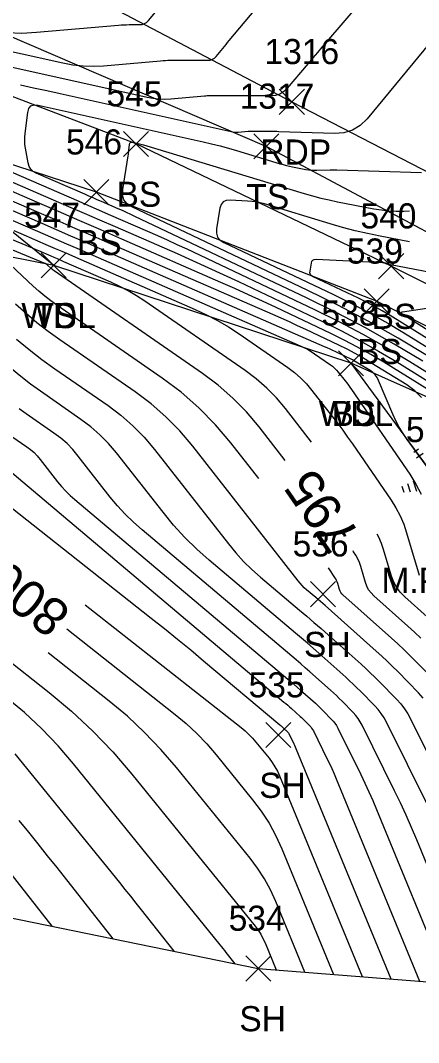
# Model space of a CAD drawing. Extents: x 1650836 to 1652450, y 332578 to 333908.
# Drawn here: x 1652260.8 to 1652292.5, y 332609.5 to 332690.8 of the extents above; entities that cross this region are included whole.
import ezdxf

# ---------------------------------------------------------------- set-up
doc = ezdxf.new("R2010")
doc.units = 0
for name, color, linetype in [('L_A', 7, 'Continuous'), ('L_C', 7, 'Continuous'), ('L_I', 7, 'Continuous'), ('L_TIC', 7, 'Continuous'), ('LAWA', 7, 'Continuous'), ('LELB', 7, 'Continuous'), ('LSOGCMA', 7, 'Continuous'), ('LSOGCMA_T', 7, 'Continuous'), ('LSOGCMI', 7, 'Continuous'), ('LSOGP', 7, 'Continuous'), ('LTC', 7, 'Continuous'), ('P_A', 7, 'Continuous'), ('P_I', 7, 'Continuous'), ('P_TIC', 7, 'Continuous'), ('PET', 7, 'Continuous')]:
    doc.layers.add(name, color=color, linetype=linetype)

msp = doc.modelspace()

# ---------------------------------------------------------------- linework, layer by layer
at = {"layer": 'L_TIC'}
for points in [[(1652268.989, 332680.007), (1652270.989, 332682.007)], [(1652270.989, 332680.007), (1652268.989, 332682.007)], [(1652279.373, 332679.816), (1652281.373, 332681.816)], [(1652281.373, 332679.816), (1652279.373, 332681.816)], [(1652265.826, 332676.17), (1652267.826, 332678.17)], [(1652267.826, 332676.17), (1652265.826, 332678.17)], [(1652262.425, 332670.343), (1652264.425, 332672.343)], [(1652264.425, 332670.343), (1652262.425, 332672.343)], [(1652262.425, 332670.343), (1652264.425, 332672.343)], [(1652264.425, 332670.343), (1652262.425, 332672.343)], [(1652289.321, 332670.283), (1652291.321, 332672.283)], [(1652291.321, 332670.283), (1652289.321, 332672.283)], [(1652288.164, 332667.483), (1652290.164, 332669.483)], [(1652290.164, 332667.483), (1652288.164, 332669.483)], [(1652286.129, 332662.549), (1652288.129, 332664.549)], [(1652288.129, 332662.549), (1652286.129, 332664.549)], [(1652286.129, 332662.549), (1652288.129, 332664.549)], [(1652288.129, 332662.549), (1652286.129, 332664.549)], [(1652283.883, 332644.163), (1652285.883, 332646.163)], [(1652285.883, 332644.163), (1652283.883, 332646.163)], [(1652280.322, 332632.943), (1652282.322, 332634.943)], [(1652282.322, 332632.943), (1652280.322, 332634.943)], [(1652278.734, 332614.362), (1652280.734, 332616.362)], [(1652280.734, 332614.362), (1652278.734, 332616.362)]]:
    msp.add_lwpolyline(points, dxfattribs=at)
at = {"layer": 'LAWA'}
msp.add_lwpolyline([(1652377.083, 332609.462), (1652362.423, 332618.359), (1652352.896, 332629.018), (1652326.723, 332645.943), (1652287.129, 332663.549), (1652263.425, 332671.343), (1652249.055, 332682.968), (1652227.219, 332684.809), (1652198.28, 332683.973), (1652188.25, 332681.448)], dxfattribs=at)
at = {"layer": 'LELB'}
for points in [[(1652226.417, 332702.923), (1652236.723, 332699.587), (1652280.373, 332680.816), (1652330.286, 332654.264), (1652363.786, 332637.255), (1652386.916, 332625.064)], [(1652382.141, 332616.979), (1652358.657, 332634.506), (1652330.255, 332651.361), (1652290.321, 332671.283), (1652269.989, 332681.007), (1652251.521, 332688.043), (1652226.806, 332692.532), (1652196.733, 332693.642), (1652183.53, 332688.882)], [(1652365.04, 332620.431), (1652356.315, 332631.256), (1652328.76, 332648.708), (1652289.164, 332668.483), (1652266.826, 332677.17), (1652249.055, 332682.968)], [(1652263.425, 332671.343), (1652250.6, 332673.853), (1652230.367, 332676.723), (1652213.745, 332678.986)], [(1652357.687, 332613.243), (1652345.655, 332623.271), (1652322.133, 332635.513), (1652299.743, 332646.435), (1652287.129, 332663.549)]]:
    msp.add_lwpolyline(points, dxfattribs=at)
at = {"layer": 'LSOGCMA'}
for points in [[(1652293.221, 332664.146), (1652290.875, 332665.556), (1652288.492, 332666.898), (1652286.072, 332668.172), (1652283.616, 332669.379), (1652269.65, 332675.996), (1652269.273, 332676.24), (1652269.026, 332676.553), (1652268.909, 332676.933), (1652268.922, 332677.383), (1652269.356, 332680.058), (1652269.374, 332680.171), (1652269.39, 332680.284), (1652269.406, 332680.397), (1652269.421, 332680.511), (1652269.479, 332680.972), (1652269.504, 332681.065), (1652269.553, 332681.124), (1652269.625, 332681.151), (1652269.721, 332681.143), (1652270.152, 332681.048), (1652270.259, 332681.023), (1652270.366, 332680.996), (1652270.473, 332680.967), (1652270.579, 332680.936), (1652283.376, 332677.07), (1652284.04, 332676.879), (1652284.707, 332676.705), (1652285.379, 332676.549), (1652286.056, 332676.41), (1652288.947, 332675.854), (1652289.538, 332675.757), (1652290.131, 332675.694), (1652290.727, 332675.663), (1652291.325, 332675.666), (1652291.78, 332675.68)], [(1652281.875, 332655.819), (1652279.794, 332658.477), (1652278.786, 332659.671), (1652277.696, 332660.779), (1652276.525, 332661.8), (1652275.274, 332662.736), (1652263.461, 332670.9), (1652263.392, 332670.95), (1652263.325, 332671.002), (1652263.26, 332671.056), (1652263.197, 332671.113), (1652262.949, 332671.344), (1652262.885, 332671.399), (1652262.817, 332671.448), (1652262.744, 332671.489), (1652262.668, 332671.525), (1652252.714, 332675.625)], [(1652292.699, 332641.652), (1652292.178, 332642.14), (1652291.649, 332642.619), (1652288.942, 332645.029), (1652288.715, 332645.261), (1652288.526, 332645.516), (1652288.375, 332645.796), (1652288.263, 332646.101), (1652287.891, 332647.366), (1652287.786, 332647.677), (1652287.657, 332647.977), (1652287.506, 332648.265), (1652287.331, 332648.543), (1652287.281, 332648.615)], [(1652264.46, 332642.402), (1652273.11, 332635.592), (1652273.992, 332634.856), (1652274.831, 332634.075), (1652275.624, 332633.249), (1652276.373, 332632.377), (1652279.277, 332628.798), (1652279.967, 332627.882), (1652280.586, 332626.923), (1652281.133, 332625.922), (1652281.608, 332624.878), (1652285.728, 332614.89)]]:
    msp.add_lwpolyline(points, dxfattribs=at)
at = {"layer": 'LSOGCMI'}
for points in [[(1652247.518, 332690.967), (1652249.349, 332690.7), (1652251.169, 332690.342), (1652264.157, 332687.455), (1652264.963, 332687.307), (1652265.774, 332687.223), (1652266.588, 332687.2), (1652267.407, 332687.241), (1652271.947, 332687.637), (1652272.139, 332687.652), (1652272.331, 332687.662), (1652272.524, 332687.669), (1652272.716, 332687.671), (1652275.7, 332687.669), (1652275.896, 332687.689), (1652276.073, 332687.748), (1652276.232, 332687.846), (1652276.372, 332687.985), (1652276.895, 332688.617), (1652277.026, 332688.775), (1652277.158, 332688.933), (1652277.289, 332689.09), (1652277.421, 332689.248), (1652283.655, 332696.668)], [(1652289.075, 332693.707), (1652285.172, 332689.147), (1652284.804, 332688.717), (1652284.438, 332688.286), (1652284.072, 332687.855), (1652283.707, 332687.423), (1652282.042, 332685.452), (1652281.762, 332685.18), (1652281.446, 332684.986), (1652281.093, 332684.87), (1652280.705, 332684.831), (1652275.884, 332684.834), (1652275.771, 332684.833), (1652275.659, 332684.829), (1652275.546, 332684.823), (1652275.433, 332684.815), (1652272.772, 332684.582), (1652272.292, 332684.559), (1652271.814, 332684.572), (1652271.339, 332684.621), (1652270.867, 332684.708), (1652251.368, 332689.042)], [(1652248.897, 332692.103), (1652257.448, 332690.202), (1652258.588, 332689.994), (1652259.733, 332689.874), (1652260.885, 332689.842), (1652262.042, 332689.899), (1652268.58, 332690.47), (1652268.792, 332690.486), (1652269.004, 332690.498), (1652269.216, 332690.505), (1652269.428, 332690.507), (1652270.278, 332690.507), (1652270.48, 332690.527), (1652270.664, 332690.588), (1652270.827, 332690.691), (1652270.972, 332690.835), (1652271.526, 332691.511)], [(1652294.668, 332690.604), (1652288.401, 332683.016), (1652287.86, 332682.484), (1652287.247, 332682.112), (1652286.562, 332681.898), (1652285.805, 332681.844), (1652281.372, 332681.986), (1652281.21, 332681.991), (1652281.048, 332681.994), (1652280.886, 332681.996), (1652280.724, 332681.997), (1652279.052, 332681.998), (1652279.019, 332681.998), (1652278.986, 332681.997), (1652278.953, 332681.995), (1652278.92, 332681.992), (1652278.137, 332681.924), (1652277.995, 332681.917), (1652277.855, 332681.921), (1652277.715, 332681.935), (1652277.576, 332681.961), (1652263.937, 332684.993), (1652262.882, 332685.227), (1652261.827, 332685.461), (1652260.772, 332685.695)], [(1652292.838, 332663.712), (1652290.574, 332665.072), (1652288.274, 332666.368), (1652285.938, 332667.598), (1652283.567, 332668.762), (1652269.892, 332675.243), (1652269.562, 332675.397), (1652269.231, 332675.549), (1652268.899, 332675.699), (1652268.566, 332675.846), (1652267.23, 332676.428), (1652266.896, 332676.573), (1652266.562, 332676.718), (1652266.228, 332676.863), (1652265.894, 332677.007), (1652262.038, 332678.674), (1652261.792, 332678.814), (1652261.601, 332678.998), (1652261.466, 332679.226), (1652261.386, 332679.498), (1652261.176, 332680.671), (1652261.135, 332680.965), (1652261.116, 332681.259), (1652261.119, 332681.554), (1652261.145, 332681.85), (1652261.353, 332683.511), (1652261.44, 332683.829), (1652261.608, 332684.033), (1652261.856, 332684.123), (1652262.185, 332684.098), (1652275.341, 332681.182), (1652276.012, 332681.027), (1652276.68, 332680.859), (1652277.345, 332680.678), (1652278.007, 332680.485), (1652281.479, 332679.436), (1652281.723, 332679.366), (1652281.969, 332679.302), (1652282.217, 332679.244), (1652282.466, 332679.193), (1652283.531, 332678.988), (1652283.749, 332678.952), (1652283.967, 332678.929), (1652284.187, 332678.918), (1652284.407, 332678.919), (1652285.472, 332678.953), (1652285.602, 332678.956), (1652285.733, 332678.957), (1652285.863, 332678.956), (1652285.993, 332678.953), (1652292.734, 332678.736)], [(1652249.728, 332682.471), (1652263.382, 332676.57), (1652264.617, 332676.036), (1652265.852, 332675.5), (1652267.086, 332674.964), (1652268.32, 332674.427), (1652273.255, 332672.277), (1652274.486, 332671.734), (1652275.714, 332671.182), (1652276.936, 332670.62), (1652278.155, 332670.049), (1652284.859, 332666.872), (1652286.37, 332666.13), (1652287.859, 332665.346), (1652289.325, 332664.52), (1652290.768, 332663.653), (1652297.985, 332659.178)], [(1652255.585, 332680.701), (1652264.638, 332676.789), (1652265.423, 332676.449), (1652266.207, 332676.109), (1652266.991, 332675.768), (1652267.775, 332675.427), (1652270.91, 332674.061), (1652271.693, 332673.717), (1652272.472, 332673.366), (1652273.249, 332673.009), (1652274.023, 332672.646), (1652284.213, 332667.817), (1652286.154, 332666.864), (1652288.066, 332665.857), (1652289.949, 332664.796), (1652291.803, 332663.682), (1652302.19, 332657.241)], [(1652294.486, 332660.676), (1652289.733, 332663.624), (1652288.7, 332664.244), (1652287.651, 332664.835), (1652286.586, 332665.396), (1652285.504, 332665.927), (1652281.146, 332667.992), (1652280.054, 332668.504), (1652278.959, 332669.008), (1652277.859, 332669.502), (1652276.756, 332669.988), (1652268.865, 332673.427), (1652267.181, 332674.16), (1652265.496, 332674.891), (1652263.811, 332675.622), (1652262.126, 332676.351), (1652252.215, 332680.635)], [(1652292.743, 332660.813), (1652292.198, 332661.355), (1652291.561, 332661.818), (1652288.698, 332663.594), (1652288.076, 332663.968), (1652287.444, 332664.324), (1652286.802, 332664.662), (1652286.15, 332664.982), (1652283.524, 332666.226), (1652282.867, 332666.535), (1652282.206, 332666.838), (1652281.544, 332667.136), (1652280.879, 332667.429), (1652268.013, 332673.035), (1652266.578, 332673.66), (1652265.142, 332674.284), (1652263.705, 332674.906), (1652262.268, 332675.528), (1652254.701, 332678.798)], [(1652283.978, 332657.277), (1652281.899, 332659.933), (1652281.18, 332660.784), (1652280.403, 332661.574), (1652279.569, 332662.302), (1652278.676, 332662.97), (1652270.681, 332668.495), (1652270.034, 332668.92), (1652269.369, 332669.311), (1652268.686, 332669.67), (1652267.985, 332669.996), (1652264.22, 332671.636), (1652263.971, 332671.744), (1652263.722, 332671.852), (1652263.474, 332671.96), (1652263.225, 332672.068), (1652262.228, 332672.499), (1652261.979, 332672.606), (1652261.73, 332672.712), (1652261.479, 332672.817), (1652261.229, 332672.92), (1652252.211, 332676.635)], [(1652294.336, 332653.747), (1652291.594, 332657.487), (1652291.266, 332657.961), (1652290.968, 332658.452), (1652290.699, 332658.959), (1652290.458, 332659.482), (1652289.316, 332662.169), (1652289.193, 332662.407), (1652289.039, 332662.618), (1652288.854, 332662.803), (1652288.637, 332662.96), (1652287.663, 332663.565), (1652287.451, 332663.692), (1652287.236, 332663.813), (1652287.018, 332663.928), (1652286.796, 332664.037), (1652285.902, 332664.46), (1652285.679, 332664.565), (1652285.454, 332664.668), (1652285.229, 332664.77), (1652285.002, 332664.869), (1652267.065, 332672.685), (1652265.926, 332673.181), (1652264.787, 332673.676), (1652263.647, 332674.17), (1652262.507, 332674.663), (1652257.188, 332676.962)], [(1652291.789, 332673.214), (1652289.451, 332673.664), (1652288.444, 332673.871), (1652287.444, 332674.104), (1652286.45, 332674.362), (1652285.463, 332674.647), (1652280.222, 332676.23), (1652279.888, 332676.32), (1652279.55, 332676.389), (1652279.209, 332676.438), (1652278.864, 332676.465), (1652277.477, 332676.534), (1652277.167, 332676.507), (1652276.93, 332676.389), (1652276.765, 332676.181), (1652276.673, 332675.884), (1652276.41, 332674.261), (1652276.399, 332673.903), (1652276.492, 332673.6), (1652276.689, 332673.352), (1652276.989, 332673.158), (1652285.661, 332669.049), (1652287.212, 332668.287), (1652288.74, 332667.482), (1652290.244, 332666.635), (1652291.725, 332665.745), (1652314.805, 332651.431)], [(1652259.374, 332675.256), (1652262.746, 332673.798), (1652263.589, 332673.433), (1652264.432, 332673.068), (1652265.275, 332672.702), (1652266.117, 332672.335), (1652283.071, 332664.948), (1652283.369, 332664.81), (1652283.659, 332664.657), (1652283.941, 332664.491), (1652284.216, 332664.311), (1652285.481, 332663.436), (1652285.655, 332663.306), (1652285.818, 332663.164), (1652285.969, 332663.01), (1652286.11, 332662.844), (1652286.648, 332662.157), (1652286.781, 332661.984), (1652286.911, 332661.809), (1652287.039, 332661.632), (1652287.164, 332661.453), (1652291.798, 332654.713), (1652292.293, 332653.93), (1652292.721, 332653.114)], [(1652260.255, 332674.112), (1652260.801, 332673.877), (1652262.985, 332672.933), (1652263.531, 332672.697), (1652264.077, 332672.46), (1652264.623, 332672.223), (1652265.168, 332671.986), (1652274.69, 332667.837), (1652275.603, 332667.413), (1652276.493, 332666.946), (1652277.358, 332666.436), (1652278.2, 332665.884), (1652282.079, 332663.203), (1652282.612, 332662.804), (1652283.111, 332662.369), (1652283.575, 332661.897), (1652284.004, 332661.389), (1652285.654, 332659.281), (1652286.062, 332658.751), (1652286.462, 332658.215), (1652286.854, 332657.673), (1652287.237, 332657.124), (1652290.309, 332652.657), (1652290.697, 332652.042), (1652291.033, 332651.402), (1652291.318, 332650.738), (1652291.55, 332650.048), (1652292.541, 332646.683)], [(1652319.01, 332649.495), (1652290.23, 332667.344), (1652289.613, 332667.714), (1652288.987, 332668.067), (1652288.352, 332668.402), (1652287.706, 332668.719), (1652284.098, 332670.428), (1652283.973, 332670.509), (1652283.891, 332670.613), (1652283.852, 332670.739), (1652283.857, 332670.888), (1652283.961, 332671.528), (1652284.004, 332671.667), (1652284.081, 332671.764), (1652284.191, 332671.819), (1652284.336, 332671.832), (1652289.624, 332671.568), (1652289.68, 332671.564), (1652289.735, 332671.556), (1652289.789, 332671.545), (1652289.843, 332671.531), (1652290.057, 332671.466), (1652290.111, 332671.45), (1652290.165, 332671.436), (1652290.219, 332671.424), (1652290.274, 332671.412), (1652300.525, 332669.443)], [(1652279.772, 332654.36), (1652277.542, 332657.209), (1652276.321, 332658.655), (1652275.001, 332659.996), (1652273.584, 332661.234), (1652272.068, 332662.367), (1652263.684, 332668.161), (1652263.189, 332668.517), (1652262.708, 332668.89), (1652262.241, 332669.28), (1652261.788, 332669.688), (1652260.005, 332671.354)], [(1652292.882, 332636.884), (1652292.488, 332637.318), (1652290.84, 332638.999), (1652290.424, 332639.415), (1652290.002, 332639.824), (1652289.573, 332640.227), (1652289.137, 332640.621), (1652285.061, 332644.249), (1652284.878, 332644.411), (1652284.694, 332644.571), (1652284.509, 332644.73), (1652284.323, 332644.888), (1652283.576, 332645.517), (1652283.394, 332645.679), (1652283.221, 332645.849), (1652283.057, 332646.028), (1652282.902, 332646.216), (1652274.503, 332656.946), (1652273.478, 332658.159), (1652272.372, 332659.284), (1652271.183, 332660.322), (1652269.912, 332661.272), (1652263.907, 332665.423), (1652262.986, 332666.084), (1652262.091, 332666.778), (1652261.222, 332667.505), (1652260.38, 332668.263)], [(1652296.859, 332663.913), (1652291.109, 332667.508), (1652291.096, 332667.519), (1652291.091, 332667.531), (1652291.093, 332667.543), (1652291.103, 332667.557), (1652291.158, 332667.613), (1652291.172, 332667.626), (1652291.188, 332667.636), (1652291.205, 332667.643), (1652291.224, 332667.647), (1652295.437, 332668.289)], [(1652260.471, 332665.47), (1652261.457, 332664.645), (1652262.472, 332663.858), (1652263.517, 332663.107), (1652267.756, 332660.177), (1652268.783, 332659.41), (1652269.743, 332658.572), (1652270.636, 332657.663), (1652271.464, 332656.684), (1652277.345, 332649.169), (1652277.935, 332648.455), (1652278.559, 332647.774), (1652279.218, 332647.126), (1652279.911, 332646.511), (1652283.022, 332643.892), (1652283.596, 332643.405), (1652284.166, 332642.915), (1652284.732, 332642.421), (1652285.296, 332641.923), (1652287.923, 332639.584), (1652288.291, 332639.251), (1652288.654, 332638.911), (1652289.011, 332638.565), (1652289.362, 332638.213), (1652290.754, 332636.794), (1652291.087, 332636.428), (1652291.387, 332636.039), (1652291.656, 332635.628), (1652291.892, 332635.193), (1652296.269, 332626.373)], [(1652293.293, 332628.225), (1652289.949, 332634.964), (1652289.756, 332635.318), (1652289.537, 332635.654), (1652289.291, 332635.971), (1652289.02, 332636.27), (1652287.884, 332637.428), (1652287.597, 332637.716), (1652287.306, 332637.998), (1652287.01, 332638.275), (1652286.709, 332638.547), (1652284.565, 332640.456), (1652284.105, 332640.862), (1652283.643, 332641.266), (1652283.178, 332641.666), (1652282.71, 332642.063), (1652275.813, 332647.868), (1652274.82, 332648.749), (1652273.876, 332649.678), (1652272.982, 332650.655), (1652272.137, 332651.679), (1652268.425, 332656.421), (1652267.794, 332657.167), (1652267.114, 332657.859), (1652266.382, 332658.498), (1652265.6, 332659.083), (1652262.371, 332661.314), (1652261.575, 332661.886), (1652260.801, 332662.486), (1652260.05, 332663.114)], [(1652297.16, 332613.99), (1652292.373, 332625.596), (1652291.955, 332626.587), (1652291.519, 332627.57), (1652291.066, 332628.546), (1652290.596, 332629.513), (1652288.006, 332634.734), (1652287.856, 332635.008), (1652287.686, 332635.268), (1652287.496, 332635.514), (1652287.286, 332635.746), (1652286.406, 332636.643), (1652286.184, 332636.866), (1652285.958, 332637.085), (1652285.729, 332637.299), (1652285.496, 332637.51), (1652283.835, 332638.989), (1652283.478, 332639.304), (1652283.12, 332639.616), (1652282.76, 332639.926), (1652282.397, 332640.234), (1652270.464, 332650.28), (1652269.781, 332650.886), (1652269.132, 332651.524), (1652268.518, 332652.195), (1652267.937, 332652.899), (1652265.386, 332656.158), (1652264.952, 332656.671), (1652264.485, 332657.147), (1652263.982, 332657.586), (1652263.444, 332657.988), (1652261.225, 332659.522), (1652260.678, 332659.915)], [(1652260.079, 332657.729), (1652261.288, 332656.893), (1652261.581, 332656.674), (1652261.855, 332656.435), (1652262.11, 332656.175), (1652262.346, 332655.896), (1652263.737, 332654.119), (1652264.054, 332653.736), (1652264.389, 332653.37), (1652264.742, 332653.022), (1652265.114, 332652.692), (1652282.084, 332638.405), (1652282.342, 332638.187), (1652282.597, 332637.967), (1652282.851, 332637.745), (1652283.104, 332637.522), (1652284.282, 332636.473), (1652284.447, 332636.324), (1652284.61, 332636.171), (1652284.77, 332636.016), (1652284.927, 332635.858), (1652285.552, 332635.222), (1652285.701, 332635.058), (1652285.836, 332634.883), (1652285.956, 332634.699), (1652286.062, 332634.504), (1652287.9, 332630.801), (1652288.233, 332630.115), (1652288.554, 332629.423), (1652288.863, 332628.726), (1652289.16, 332628.023), (1652294.874, 332614.17)], [(1652259.765, 332655.103), (1652281.772, 332636.576), (1652281.924, 332636.447), (1652282.074, 332636.317), (1652282.224, 332636.187), (1652282.373, 332636.055), (1652283.069, 332635.436), (1652283.166, 332635.348), (1652283.262, 332635.258), (1652283.356, 332635.166), (1652283.449, 332635.073), (1652283.818, 332634.698), (1652283.906, 332634.601), (1652283.985, 332634.498), (1652284.056, 332634.389), (1652284.119, 332634.274), (1652285.203, 332632.09), (1652285.4, 332631.685), (1652285.589, 332631.276), (1652285.771, 332630.865), (1652285.947, 332630.45), (1652292.587, 332614.35)], [(1652259.502, 332652.479), (1652271.204, 332643.265), (1652272.258, 332642.429), (1652273.305, 332641.584), (1652274.344, 332640.73), (1652275.377, 332639.868), (1652281.459, 332634.747), (1652281.506, 332634.708), (1652281.552, 332634.668), (1652281.597, 332634.628), (1652281.643, 332634.588), (1652281.855, 332634.399), (1652281.885, 332634.372), (1652281.914, 332634.345), (1652281.943, 332634.317), (1652281.971, 332634.288), (1652282.084, 332634.174), (1652282.11, 332634.144), (1652282.135, 332634.113), (1652282.156, 332634.079), (1652282.176, 332634.044), (1652282.506, 332633.378), (1652282.566, 332633.254), (1652282.624, 332633.13), (1652282.68, 332633.004), (1652282.733, 332632.877), (1652290.301, 332614.53)], [(1652293.204, 332643.353), (1652291.412, 332644.948), (1652291.046, 332645.321), (1652290.742, 332645.732), (1652290.5, 332646.182), (1652290.32, 332646.672), (1652289.72, 332648.707), (1652289.552, 332649.207), (1652289.345, 332649.689), (1652289.208, 332649.952)], [(1652294.223, 332637.842), (1652292.318, 332639.784), (1652291.838, 332640.265), (1652291.35, 332640.738), (1652290.854, 332641.202), (1652290.35, 332641.659), (1652286.472, 332645.11), (1652286.383, 332645.201), (1652286.31, 332645.301), (1652286.251, 332645.411), (1652286.207, 332645.53), (1652286.061, 332646.025), (1652286.02, 332646.147), (1652285.969, 332646.264), (1652285.91, 332646.377), (1652285.842, 332646.486), (1652285.371, 332647.171), (1652285.314, 332647.252)], [(1652265.943, 332644.321), (1652278.371, 332634.536), (1652278.689, 332634.271), (1652278.99, 332633.991), (1652279.275, 332633.694), (1652279.544, 332633.381), (1652280.587, 332632.095), (1652280.835, 332631.766), (1652281.058, 332631.421), (1652281.254, 332631.061), (1652281.425, 332630.686), (1652288.014, 332614.71)], [(1652255.653, 332643.162), (1652263.056, 332637.334), (1652264.841, 332635.847), (1652266.536, 332634.268), (1652268.14, 332632.597), (1652269.653, 332630.834), (1652279.481, 332618.725), (1652279.713, 332618.417), (1652279.922, 332618.094), (1652280.106, 332617.756), (1652280.266, 332617.404), (1652281.155, 332615.25)], [(1652283.441, 332615.07), (1652281.123, 332620.692), (1652280.705, 332621.61), (1652280.224, 332622.491), (1652279.679, 332623.334), (1652279.072, 332624.139), (1652273.201, 332631.373), (1652271.973, 332632.804), (1652270.672, 332634.16), (1652269.296, 332635.441), (1652267.848, 332636.648), (1652262.976, 332640.483)], [(1652277.89, 332615.739), (1652277.179, 332616.641), (1652277.06, 332616.791), (1652276.941, 332616.941), (1652276.821, 332617.09), (1652276.701, 332617.239), (1652265.006, 332631.648), (1652263.774, 332633.084), (1652262.468, 332634.444), (1652261.088, 332635.73), (1652259.635, 332636.941)], [(1652273.022, 332616.735), (1652270.434, 332620.018), (1652270.002, 332620.565), (1652269.567, 332621.11), (1652269.131, 332621.653), (1652268.693, 332622.195), (1652260.359, 332632.463)], [(1652255.939, 332628.046), (1652263.286, 332618.727)], [(1652268.154, 332617.731), (1652263.689, 332623.395), (1652262.943, 332624.338), (1652262.194, 332625.278), (1652261.441, 332626.215), (1652260.685, 332627.15)]]:
    msp.add_lwpolyline(points, dxfattribs=at)
at = {"layer": 'LSOGP'}
msp.add_lwpolyline([(1652132.417, 332639.149), (1652165.837, 332638.134), (1652188.754, 332630.096), (1652208.992, 332628.311), (1652238.609, 332623.775), (1652279.734, 332615.362), (1652315.79, 332612.523)], dxfattribs=at)
at = {"layer": 'LTC'}
for p, q in [((1652292.135, 332656.478), (1652292.489, 332656.735)), ((1652292.344, 332656.012), (1652292.874, 332656.396)), ((1652291.623, 332653.973), (1652291.834, 332653.322)), ((1652292.078, 332654.19), (1652292.349, 332653.355)), ((1652291.167, 332653.757), (1652291.319, 332653.289))]:
    msp.add_line(p, q, dxfattribs=at)
at = {"layer": 'P_TIC'}
for points in [[(1652281.404, 332683.366), (1652283.404, 332685.366)], [(1652283.404, 332683.366), (1652281.404, 332685.366)]]:
    msp.add_lwpolyline(points, dxfattribs=at)
at = {"layer": 'PET'}
msp.add_lwpolyline([(1651764.546, 332972.615), (1651784.506, 332958.597), (1651809.702, 332941.927), (1651846.26, 332918.158), (1651881.765, 332897.162), (1651918.116, 332876.642), (1651951.432, 332858.415), (1651975.296, 332845.48), (1652002.223, 332831.337), (1652037.173, 332813.417), (1652069.296, 332796.636), (1652107.428, 332776.545), (1652145.079, 332756.921), (1652175.234, 332740.226), (1652190.754, 332731.861), (1652206.573, 332723.523), (1652239.422, 332706.921), (1652282.404, 332684.366), (1652332.494, 332658.525), (1652365.542, 332641.171), (1652388.914, 332629.021)], dxfattribs=at)

# ---------------------------------------------------------------- texts
at = {"layer": 'L_A'}
for s, p in [('BS', (1652268.43, 332676.007)), ('TS', (1652278.782, 332675.816)), ('BS', (1652265.267, 332672.17)), ('WDL', (1652260.842, 332666.343)), ('TS', (1652261.835, 332666.343)), ('BS', (1652288.762, 332666.283)), ('BS', (1652287.605, 332663.483)), ('WDL', (1652284.546, 332658.549)), ('BS', (1652285.57, 332658.549)), ('SH', (1652283.372, 332640.163)), ('SH', (1652279.81, 332628.943)), ('SH', (1652278.222, 332610.362))]:
    msp.add_text(s, height=2, dxfattribs=at).set_placement(p)
at = {"layer": 'L_C'}
msp.add_text('M.PINE', height=2, dxfattribs=at).set_placement((1652289.546, 332645.269))
at = {"layer": 'L_I'}
for s, p in [('545', (1652267.627, 332684.007)), ('1317', (1652278.247, 332683.816)), ('546', (1652264.409, 332680.17)), ('547', (1652261.063, 332674.343)), ('547', (1652261.063, 332674.343)), ('540', (1652287.873, 332674.283)), ('539', (1652286.794, 332671.483)), ('538', (1652284.767, 332666.549)), ('538', (1652284.767, 332666.549)), ('504', (1652291.499, 332657.269)), ('536', (1652282.466, 332648.163)), ('535', (1652278.96, 332636.943)), ('534', (1652277.372, 332618.362))]:
    msp.add_text(s, height=2, dxfattribs=at).set_placement(p)
at = {"layer": 'LSOGCMA_T'}
for s, rotation, p in [('795', 124.74174, (1652287.924, 332649.881)), ('800', 142.28706, (1652264.939, 332643.911))]:
    msp.add_text(s, height=3, rotation=rotation, dxfattribs=at).set_placement(p)
at = {"layer": 'P_A'}
msp.add_text('RDP', height=2, dxfattribs=at).set_placement((1652279.892, 332679.366))
at = {"layer": 'P_I'}
msp.add_text('1316', height=2, dxfattribs=at).set_placement((1652280.223, 332687.366))

doc.saveas('drawing.dxf')
